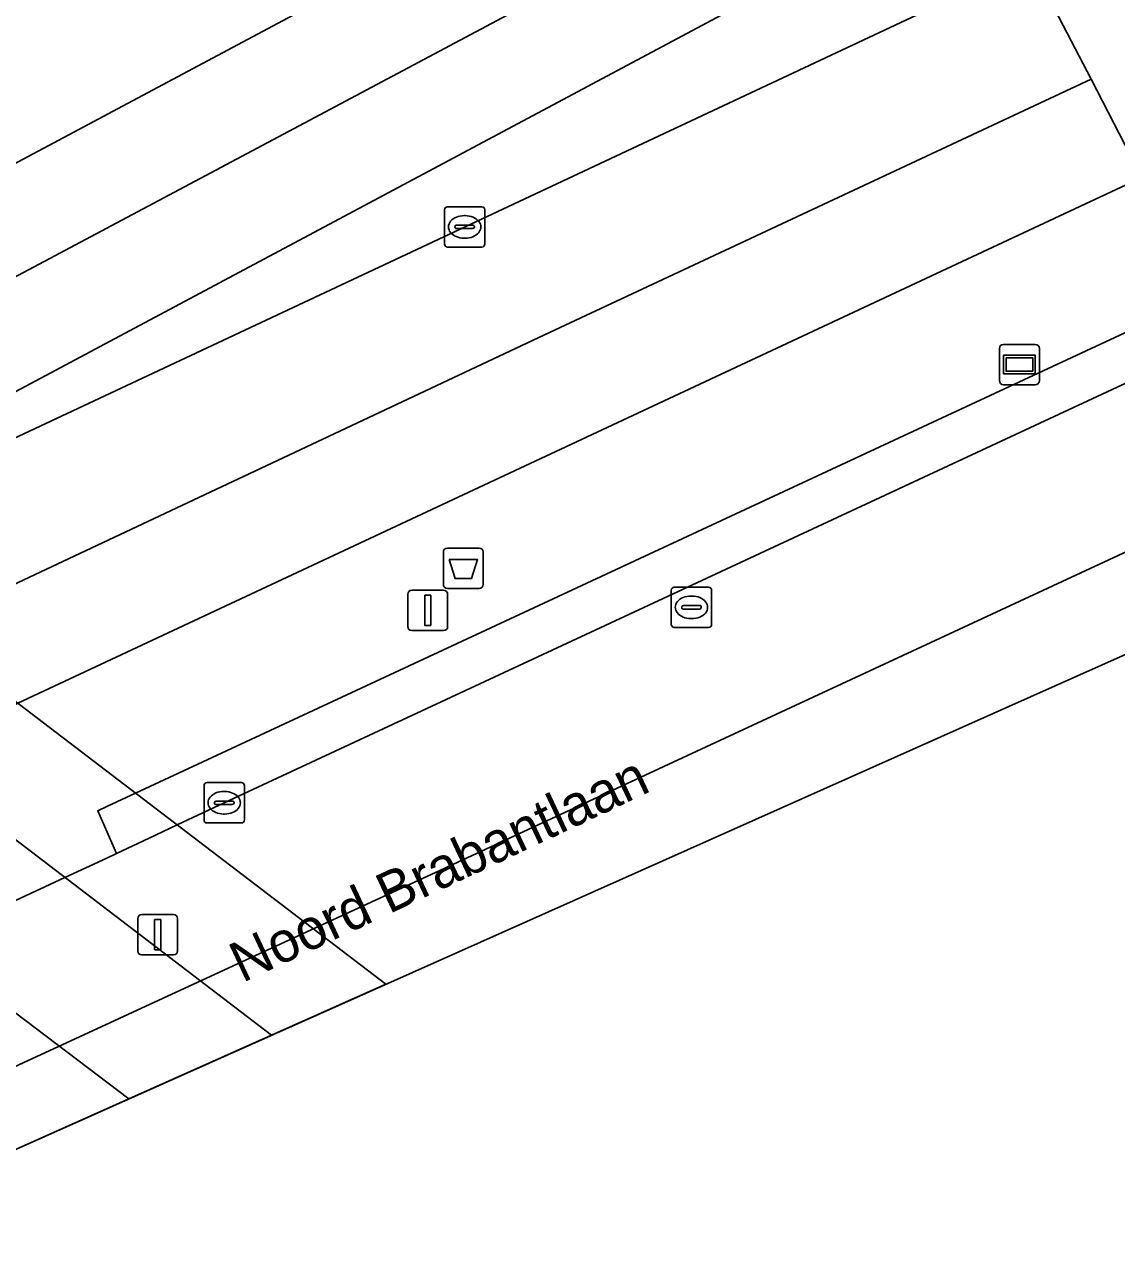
# Model space of a CAD drawing. Extents: x 158352 to 159489, y 383828 to 384603.
# Drawn here: x 158893.95 to 158921.02, y 383828 to 383858.39 of the extents above; entities that cross this region are included whole.
import ezdxf

# ---------------------------------------------------------------- set-up
doc = ezdxf.new("R2010")
doc.units = 0
for name, color, linetype in [('IMGEO_Afvalbak', 7, 'Continuous'), ('IMGEO_Berm_gesloten', 7, 'Continuous'), ('IMGEO_Berm_groen', 7, 'Continuous'), ('IMGEO_Berm_open', 7, 'Continuous'), ('IMGEO_Dek', 7, 'Continuous'), ('IMGEO_Fietspad_gesloten', 7, 'Continuous'), ('IMGEO_Hek', 7, 'Continuous'), ('IMGEO_Kolk', 7, 'Continuous'), ('IMGEO_Lichtmast', 7, 'Continuous'), ('IMGEO_Openbare_ruimte_label', 7, 'Continuous'), ('IMGEO_OVBaan_gesloten', 7, 'Continuous'), ('IMGEO_Rijbaan_regionaal_gesloten', 7, 'Continuous'), ('IMGEO_Voetpad_open', 7, 'Continuous'), ('IMGEO_Wegwijzer', 7, 'Continuous')]:
    doc.layers.add(name, color=color, linetype=linetype)

msp = doc.modelspace()

# ---------------------------------------------------------------- linework, layer by layer
at = {"layer": 'IMGEO_Afvalbak'}
for p, q in [((158904.435, 383845.401), (158905.225, 383845.401)), ((158905.225, 383845.401), (158904.435, 383845.401)), ((158904.335, 383844.501), (158904.335, 383845.301)), ((158904.335, 383845.301), (158904.335, 383844.501)), ((158905.325, 383845.301), (158905.325, 383844.501)), ((158905.325, 383844.501), (158905.325, 383845.301)), ((158905.225, 383844.401), (158904.435, 383844.401)), ((158904.435, 383844.401), (158905.225, 383844.401))]:
    msp.add_line(p, q, dxfattribs=at)
msp.add_lwpolyline([(158904.478, 383845.115), (158905.182, 383845.115), (158905.033, 383844.645), (158904.627, 383844.645), (158904.478, 383845.115)], dxfattribs=at)
for centre, start, end in [((158904.435, 383845.301), 90, 180), ((158904.435, 383845.301), 90, 180), ((158905.225, 383845.301), 0, 90), ((158905.225, 383845.301), 360, 90), ((158904.435, 383844.501), 180, 270), ((158904.435, 383844.501), 180, 270), ((158905.225, 383844.501), 270, 0), ((158905.225, 383844.501), 270, 0)]:
    msp.add_arc(centre, 0.1, start, end, dxfattribs=at)
at = {"layer": 'IMGEO_Berm_gesloten'}
msp.add_lwpolyline([(158902.912, 383834.582), (158882.404, 383850.241), (158881.596, 383849.718), (158879.982, 383848.672), (158900.074, 383833.316)], close=True, dxfattribs=at)
at = {"layer": 'IMGEO_Berm_groen'}
msp.add_lwpolyline([(158883.34, 383875.673), (158883.199, 383875.722), (158882.767, 383874.369), (158884.881, 383873.33), (158887.482, 383869.723), (158886.442, 383864.681), (158886.793, 383863.483), (158888.248, 383863.669), (158890.986, 383858.707), (158892.577, 383857.59), (158888.098, 383851.946), (158911.983, 383864.702)], dxfattribs=at)
at = {"layer": 'IMGEO_Berm_open'}
for points in [[(158917.865, 383862.123), (158916.911, 383861.665), (158889.778, 383847.177), (158888.336, 383846.413), (158887.766, 383846.147), (158887.071, 383845.822), (158884.987, 383844.847), (158881.597, 383843.26), (158877.829, 383841.497), (158877.205, 383841.205), (158875.569, 383840.439), (158875.237, 383840.284), (158873.273, 383839.365), (158873.923, 383838.869)], [(158873.923, 383838.869), (158875.878, 383839.792), (158876.212, 383839.95), (158877.849, 383840.715), (158878.47, 383841.006), (158882.238, 383842.768), (158885.631, 383844.355), (158887.715, 383845.33), (158888.411, 383845.655), (158892.868, 383847.74), (158917.95, 383859.51), (158918.9, 383859.914)]]:
    msp.add_lwpolyline(points, dxfattribs=at)
at = {"layer": 'IMGEO_Dek'}
msp.add_lwpolyline([(158888.17, 383828.002), (158902.912, 383834.582), (158882.404, 383850.241), (158881.596, 383849.718), (158879.982, 383848.672), (158879.879, 383848.751), (158872.742, 383845.398), (158870.149, 383844.179), (158868.176, 383843.252)], close=True, dxfattribs=at)
at = {"layer": 'IMGEO_Fietspad_gesloten'}
for points in [[(158928.847, 383870.049), (158920.435, 383866.116), (158916.837, 383864.363), (158913.261, 383862.538), (158888.496, 383849.349), (158887.175, 383848.641), (158885.524, 383847.859), (158884.828, 383847.535), (158882.745, 383846.561), (158879.36, 383844.978), (158875.589, 383843.214), (158874.956, 383842.918), (158873.317, 383842.151), (158872.995, 383842), (158871.026, 383841.079), (158873.273, 383839.365)], [(158873.273, 383839.365), (158875.237, 383840.284), (158875.569, 383840.439), (158877.205, 383841.205), (158877.829, 383841.497), (158881.597, 383843.26), (158884.987, 383844.847), (158887.071, 383845.822), (158887.766, 383846.147), (158888.336, 383846.413), (158889.778, 383847.177), (158916.911, 383861.665), (158917.865, 383862.123), (158921.001, 383863.594)]]:
    msp.add_lwpolyline(points, dxfattribs=at)
at = {"layer": 'IMGEO_Hek'}
msp.add_lwpolyline([(158882.404, 383850.241), (158902.912, 383834.582)], dxfattribs=at)
at = {"layer": 'IMGEO_Kolk'}
for p, q in [((158904.438, 383853.868), (158905.29, 383853.868)), ((158904.363, 383852.942), (158904.363, 383853.794)), ((158904.851, 383853.648), (158904.876, 383853.648)), ((158905.364, 383853.794), (158905.364, 383852.942)), ((158904.622, 383853.362), (158904.622, 383853.374)), ((158905.06, 383853.325), (158904.662, 383853.325)), ((158904.665, 383853.411), (158905.063, 383853.411)), ((158905.106, 383853.374), (158905.106, 383853.362)), ((158904.874, 383853.088), (158904.849, 383853.088)), ((158905.29, 383852.868), (158904.438, 383852.868)), ((158910.06, 383844.432), (158910.912, 383844.432)), ((158909.985, 383843.506), (158909.985, 383844.358)), ((158910.473, 383844.212), (158910.498, 383844.212)), ((158910.986, 383844.358), (158910.986, 383843.506)), ((158910.244, 383843.926), (158910.244, 383843.938)), ((158910.682, 383843.889), (158910.284, 383843.889)), ((158910.287, 383843.975), (158910.685, 383843.975)), ((158910.728, 383843.938), (158910.728, 383843.926)), ((158910.496, 383843.652), (158910.471, 383843.652)), ((158910.912, 383843.432), (158910.06, 383843.432)), ((158898.478, 383839.584), (158899.33, 383839.584)), ((158898.403, 383838.658), (158898.403, 383839.51)), ((158898.891, 383839.364), (158898.916, 383839.364)), ((158899.404, 383839.51), (158899.404, 383838.658)), ((158898.662, 383839.078), (158898.662, 383839.09)), ((158899.1, 383839.041), (158898.702, 383839.041)), ((158898.705, 383839.127), (158899.103, 383839.127)), ((158899.146, 383839.09), (158899.146, 383839.078)), ((158898.914, 383838.804), (158898.889, 383838.804)), ((158899.33, 383838.584), (158898.478, 383838.584))]:
    msp.add_line(p, q, dxfattribs=at)
for points in [[(158904.438, 383853.868), (158905.29, 383853.868)], [(158904.363, 383852.942), (158904.363, 383853.794)], [(158905.364, 383853.794), (158905.364, 383852.942)], [(158905.29, 383852.868), (158904.438, 383852.868)], [(158910.06, 383844.432), (158910.912, 383844.432)], [(158909.985, 383843.506), (158909.985, 383844.358)], [(158910.986, 383844.358), (158910.986, 383843.506)], [(158910.912, 383843.432), (158910.06, 383843.432)], [(158898.478, 383839.584), (158899.33, 383839.584)], [(158898.403, 383838.658), (158898.403, 383839.51)], [(158899.404, 383839.51), (158899.404, 383838.658)], [(158899.33, 383838.584), (158898.478, 383838.584)]]:
    msp.add_lwpolyline(points, dxfattribs=at)
for centre, radius, start, end in [((158904.44, 383853.792), 0.0765, 91.552, 178.448), ((158904.44, 383853.792), 0.0765, 91.552, 178.448), ((158905.288, 383853.792), 0.0765, 1.552, 88.448), ((158905.288, 383853.792), 0.0765, 1.552, 88.448), ((158904.662, 383853.371), 0.0403, 85.8775, 175.7526), ((158904.659, 383853.361), 0.0366, 178.938, 274.7102), ((158905.063, 383853.368), 0.043, 264.8664, 352.4533), ((158905.067, 383853.373), 0.0386, 1.7309, 96.639), ((158904.44, 383852.944), 0.0765, 181.552, 268.448), ((158904.44, 383852.944), 0.0765, 181.552, 268.448), ((158905.288, 383852.944), 0.0765, 271.552, 358.448), ((158905.288, 383852.944), 0.0765, 271.552, 358.448), ((158910.062, 383844.356), 0.0765, 91.552, 178.448), ((158910.062, 383844.356), 0.0765, 91.552, 178.448), ((158910.91, 383844.356), 0.0765, 1.552, 88.448), ((158910.91, 383844.356), 0.0765, 1.552, 88.448), ((158910.284, 383843.935), 0.0403, 85.8775, 175.7526), ((158910.281, 383843.925), 0.0366, 178.938, 274.7102), ((158910.685, 383843.932), 0.043, 264.8664, 352.4533), ((158910.689, 383843.937), 0.0386, 1.7309, 96.639), ((158910.062, 383843.508), 0.0765, 181.552, 268.448), ((158910.062, 383843.508), 0.0765, 181.552, 268.448), ((158910.91, 383843.508), 0.0765, 271.552, 358.448), ((158910.91, 383843.508), 0.0765, 271.552, 358.448), ((158898.48, 383839.508), 0.0765, 91.552, 178.448), ((158898.48, 383839.508), 0.0765, 91.552, 178.448), ((158899.328, 383839.508), 0.0765, 1.552, 88.448), ((158899.328, 383839.508), 0.0765, 1.552, 88.448), ((158898.702, 383839.087), 0.0403, 85.8775, 175.7526), ((158898.699, 383839.077), 0.0366, 178.938, 274.7102), ((158899.103, 383839.084), 0.043, 264.8664, 352.4533), ((158899.107, 383839.089), 0.0386, 1.7309, 96.639), ((158898.48, 383838.66), 0.0765, 181.552, 268.448), ((158898.48, 383838.66), 0.0765, 181.552, 268.448), ((158899.328, 383838.66), 0.0765, 271.552, 358.448), ((158899.328, 383838.66), 0.0765, 271.552, 358.448)]:
    msp.add_arc(centre, radius, start, end, dxfattribs=at)
for centre, major_axis, ratio, start_param, end_param in [((158904.85, 383853.368), (-0.387, 0.002), 0.722429, 4.712389, 7.853982), ((158904.875, 383853.368), (-0.39, 0.002), 0.717154, 1.570796, 4.712389), ((158910.472, 383843.932), (-0.387, 0.002), 0.722429, 4.712389, 7.853982), ((158910.497, 383843.932), (-0.39, 0.002), 0.717154, 1.570796, 4.712389), ((158898.89, 383839.084), (-0.387, 0.002), 0.722429, 4.712389, 7.853982), ((158898.915, 383839.084), (-0.39, 0.002), 0.717154, 1.570796, 4.712389)]:
    msp.add_ellipse(centre, major_axis=major_axis, ratio=ratio, start_param=start_param, end_param=end_param, dxfattribs=at)
at = {"layer": 'IMGEO_Lichtmast'}
for p, q in [((158903.452, 383843.456), (158903.452, 383844.256)), ((158903.452, 383844.256), (158903.452, 383843.456)), ((158903.552, 383844.356), (158904.342, 383844.356)), ((158904.342, 383844.356), (158903.552, 383844.356)), ((158904.442, 383844.256), (158904.442, 383843.456)), ((158904.442, 383843.456), (158904.442, 383844.256)), ((158904.342, 383843.356), (158903.552, 383843.356)), ((158903.552, 383843.356), (158904.342, 383843.356)), ((158896.758, 383835.411), (158896.758, 383836.211)), ((158896.758, 383836.211), (158896.758, 383835.411)), ((158896.858, 383836.311), (158897.648, 383836.311)), ((158897.648, 383836.311), (158896.858, 383836.311)), ((158897.748, 383836.211), (158897.748, 383835.411)), ((158897.748, 383835.411), (158897.748, 383836.211)), ((158897.648, 383835.311), (158896.858, 383835.311)), ((158896.858, 383835.311), (158897.648, 383835.311))]:
    msp.add_line(p, q, dxfattribs=at)
for points in [[(158903.872, 383844.231), (158904.022, 383844.231), (158904.022, 383843.481), (158903.872, 383843.481), (158903.872, 383844.231)], [(158897.178, 383836.186), (158897.328, 383836.186), (158897.328, 383835.436), (158897.178, 383835.436), (158897.178, 383836.186)]]:
    msp.add_lwpolyline(points, dxfattribs=at)
for centre, start, end in [((158903.552, 383844.256), 90, 180), ((158903.552, 383844.256), 90, 180), ((158904.342, 383844.256), 0, 90), ((158904.342, 383844.256), 360, 90), ((158903.552, 383843.456), 180, 270), ((158903.552, 383843.456), 180, 270), ((158904.342, 383843.456), 270, 0), ((158904.342, 383843.456), 270, 0), ((158896.858, 383836.211), 90, 180), ((158896.858, 383836.211), 90, 180), ((158897.648, 383836.211), 0, 90), ((158897.648, 383836.211), 360, 90), ((158896.858, 383835.411), 180, 270), ((158896.858, 383835.411), 180, 270), ((158897.648, 383835.411), 270, 0), ((158897.648, 383835.411), 270, 0)]:
    msp.add_arc(centre, 0.1, start, end, dxfattribs=at)
at = {"layer": 'IMGEO_OVBaan_gesloten'}
msp.add_lwpolyline([(158886.555, 383829.234), (158901.164, 383835.98), (158904.461, 383837.5), (158925.248, 383847.161), (158923.544, 383850.563), (158898.905, 383839.083), (158897.738, 383838.533), (158897.043, 383838.205), (158896.233, 383837.824), (158895.996, 383837.712), (158894.954, 383837.229), (158891.523, 383835.638), (158887.752, 383833.889), (158887.164, 383833.616), (158885.536, 383832.859), (158885.16, 383832.685), (158884.88, 383832.556), (158883.218, 383831.779), (158886.555, 383829.234)], dxfattribs=at)
msp.add_lwpolyline([(158886.555, 383829.234), (158888.17, 383828.002), (158926.315, 383845.029), (158925.248, 383847.161), (158904.461, 383837.5), (158901.164, 383835.98)], close=True, dxfattribs=at)
at = {"layer": 'IMGEO_Rijbaan_regionaal_gesloten'}
msp.add_lwpolyline([(158932.916, 383866.466), (158931.792, 383865.95), (158925.15, 383862.845), (158922.022, 383861.386), (158918.9, 383859.914), (158920.391, 383857.032), (158921.65, 383854.598), (158924.717, 383856.017), (158924.816, 383856.059), (158927.984, 383857.264)], dxfattribs=at)
for points in [[(158876.859, 383836.63), (158891.4, 383843.427), (158906.968, 383850.752), (158920.391, 383857.032), (158918.9, 383859.914), (158917.95, 383859.51), (158892.868, 383847.74), (158888.411, 383845.655), (158887.715, 383845.33), (158885.631, 383844.355), (158882.238, 383842.768), (158878.47, 383841.006), (158877.849, 383840.715), (158876.212, 383839.95), (158875.878, 383839.792), (158873.923, 383838.869)], [(158879.303, 383834.765), (158881.252, 383835.678), (158881.609, 383835.845), (158883.237, 383836.609), (158883.837, 383836.89), (158887.597, 383838.652), (158891.004, 383840.248), (158893.089, 383841.225), (158893.784, 383841.552), (158905.214, 383846.907), (158921.65, 383854.598), (158920.391, 383857.032), (158906.968, 383850.752), (158891.4, 383843.427), (158876.859, 383836.63)], [(158900.074, 383833.316), (158879.982, 383848.672), (158879.879, 383848.751), (158876.311, 383847.075), (158896.539, 383831.738)], [(158896.539, 383831.738), (158876.311, 383847.075), (158872.742, 383845.398), (158892.759, 383830.05)]]:
    msp.add_lwpolyline(points, close=True, dxfattribs=at)
at = {"layer": 'IMGEO_Voetpad_open'}
for points in [[(158871.026, 383841.079), (158872.995, 383842), (158873.317, 383842.151), (158874.956, 383842.918), (158875.589, 383843.214), (158879.36, 383844.978), (158882.745, 383846.561), (158884.828, 383847.535), (158885.524, 383847.859), (158887.175, 383848.641), (158888.496, 383849.349), (158913.261, 383862.538), (158916.837, 383864.363), (158920.435, 383866.116), (158928.847, 383870.049)], [(158911.983, 383864.702), (158888.098, 383851.946), (158886.099, 383849.427), (158884.467, 383848.666), (158881.685, 383847.37), (158874.523, 383844.032), (158871.922, 383842.821), (158869.948, 383841.901), (158871.026, 383841.079)], [(158921.65, 383854.598), (158905.214, 383846.907), (158893.784, 383841.552), (158893.089, 383841.225), (158891.004, 383840.248), (158887.597, 383838.652), (158883.837, 383836.89), (158883.237, 383836.609), (158881.609, 383835.845), (158881.252, 383835.678), (158879.303, 383834.765), (158883.218, 383831.779)], [(158883.218, 383831.779), (158884.88, 383832.556), (158885.16, 383832.685), (158885.536, 383832.859), (158887.164, 383833.616), (158887.752, 383833.889), (158891.523, 383835.638), (158894.954, 383837.229), (158895.996, 383837.712), (158896.233, 383837.824), (158895.768, 383838.886), (158896.007, 383838.997), (158896.704, 383839.322), (158923.487, 383851.789), (158922.233, 383854.347)], [(158923.765, 383851.222), (158923.487, 383851.789), (158896.704, 383839.322), (158896.007, 383838.997), (158895.768, 383838.886), (158896.233, 383837.824), (158897.043, 383838.205), (158897.738, 383838.533), (158898.905, 383839.083), (158923.544, 383850.563)]]:
    msp.add_lwpolyline(points, dxfattribs=at)
at = {"layer": 'IMGEO_Wegwijzer'}
for p, q in [((158918.12, 383849.554), (158918.12, 383850.354)), ((158918.12, 383850.354), (158918.12, 383849.554)), ((158918.22, 383850.454), (158919.01, 383850.454)), ((158919.01, 383850.454), (158918.22, 383850.454)), ((158919.11, 383850.354), (158919.11, 383849.554)), ((158919.11, 383849.554), (158919.11, 383850.354)), ((158919.01, 383849.454), (158918.22, 383849.454)), ((158918.22, 383849.454), (158919.01, 383849.454))]:
    msp.add_line(p, q, dxfattribs=at)
for points in [[(158918.221, 383850.186), (158919.009, 383850.186), (158919.009, 383849.722), (158918.221, 383849.722), (158918.221, 383850.186)], [(158918.286, 383850.121), (158918.286, 383849.787), (158918.944, 383849.787), (158918.944, 383850.121), (158918.286, 383850.121)]]:
    msp.add_lwpolyline(points, dxfattribs=at)
for centre, start, end in [((158918.22, 383850.354), 90, 180), ((158918.22, 383850.354), 90, 180), ((158919.01, 383850.354), 0, 90), ((158919.01, 383850.354), 360, 90), ((158918.22, 383849.554), 180, 270), ((158918.22, 383849.554), 180, 270), ((158919.01, 383849.554), 270, 0), ((158919.01, 383849.554), 270, 0)]:
    msp.add_arc(centre, 0.1, start, end, dxfattribs=at)

# ---------------------------------------------------------------- texts
at = {"layer": 'IMGEO_Openbare_ruimte_label'}
msp.add_text('Noord Brabantlaan', height=1, rotation=25.1554, dxfattribs=at).set_placement((158899.352, 383834.61))

doc.saveas('drawing.dxf')
